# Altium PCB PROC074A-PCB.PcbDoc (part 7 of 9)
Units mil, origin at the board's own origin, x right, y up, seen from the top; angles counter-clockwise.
Board outline 2755.91 x 5300 mil, 10 copper layers (Top Layer, L2-GND, L3-SIG1, L4-GND, L5-PWR/SIG, L6-SIG2, L7-PWR2, L8-SIG3, L9-GND, Bottom Layer), stack 67.57 mil thick; 585 components, 490 nets, 2137 pads, 1150 vias.
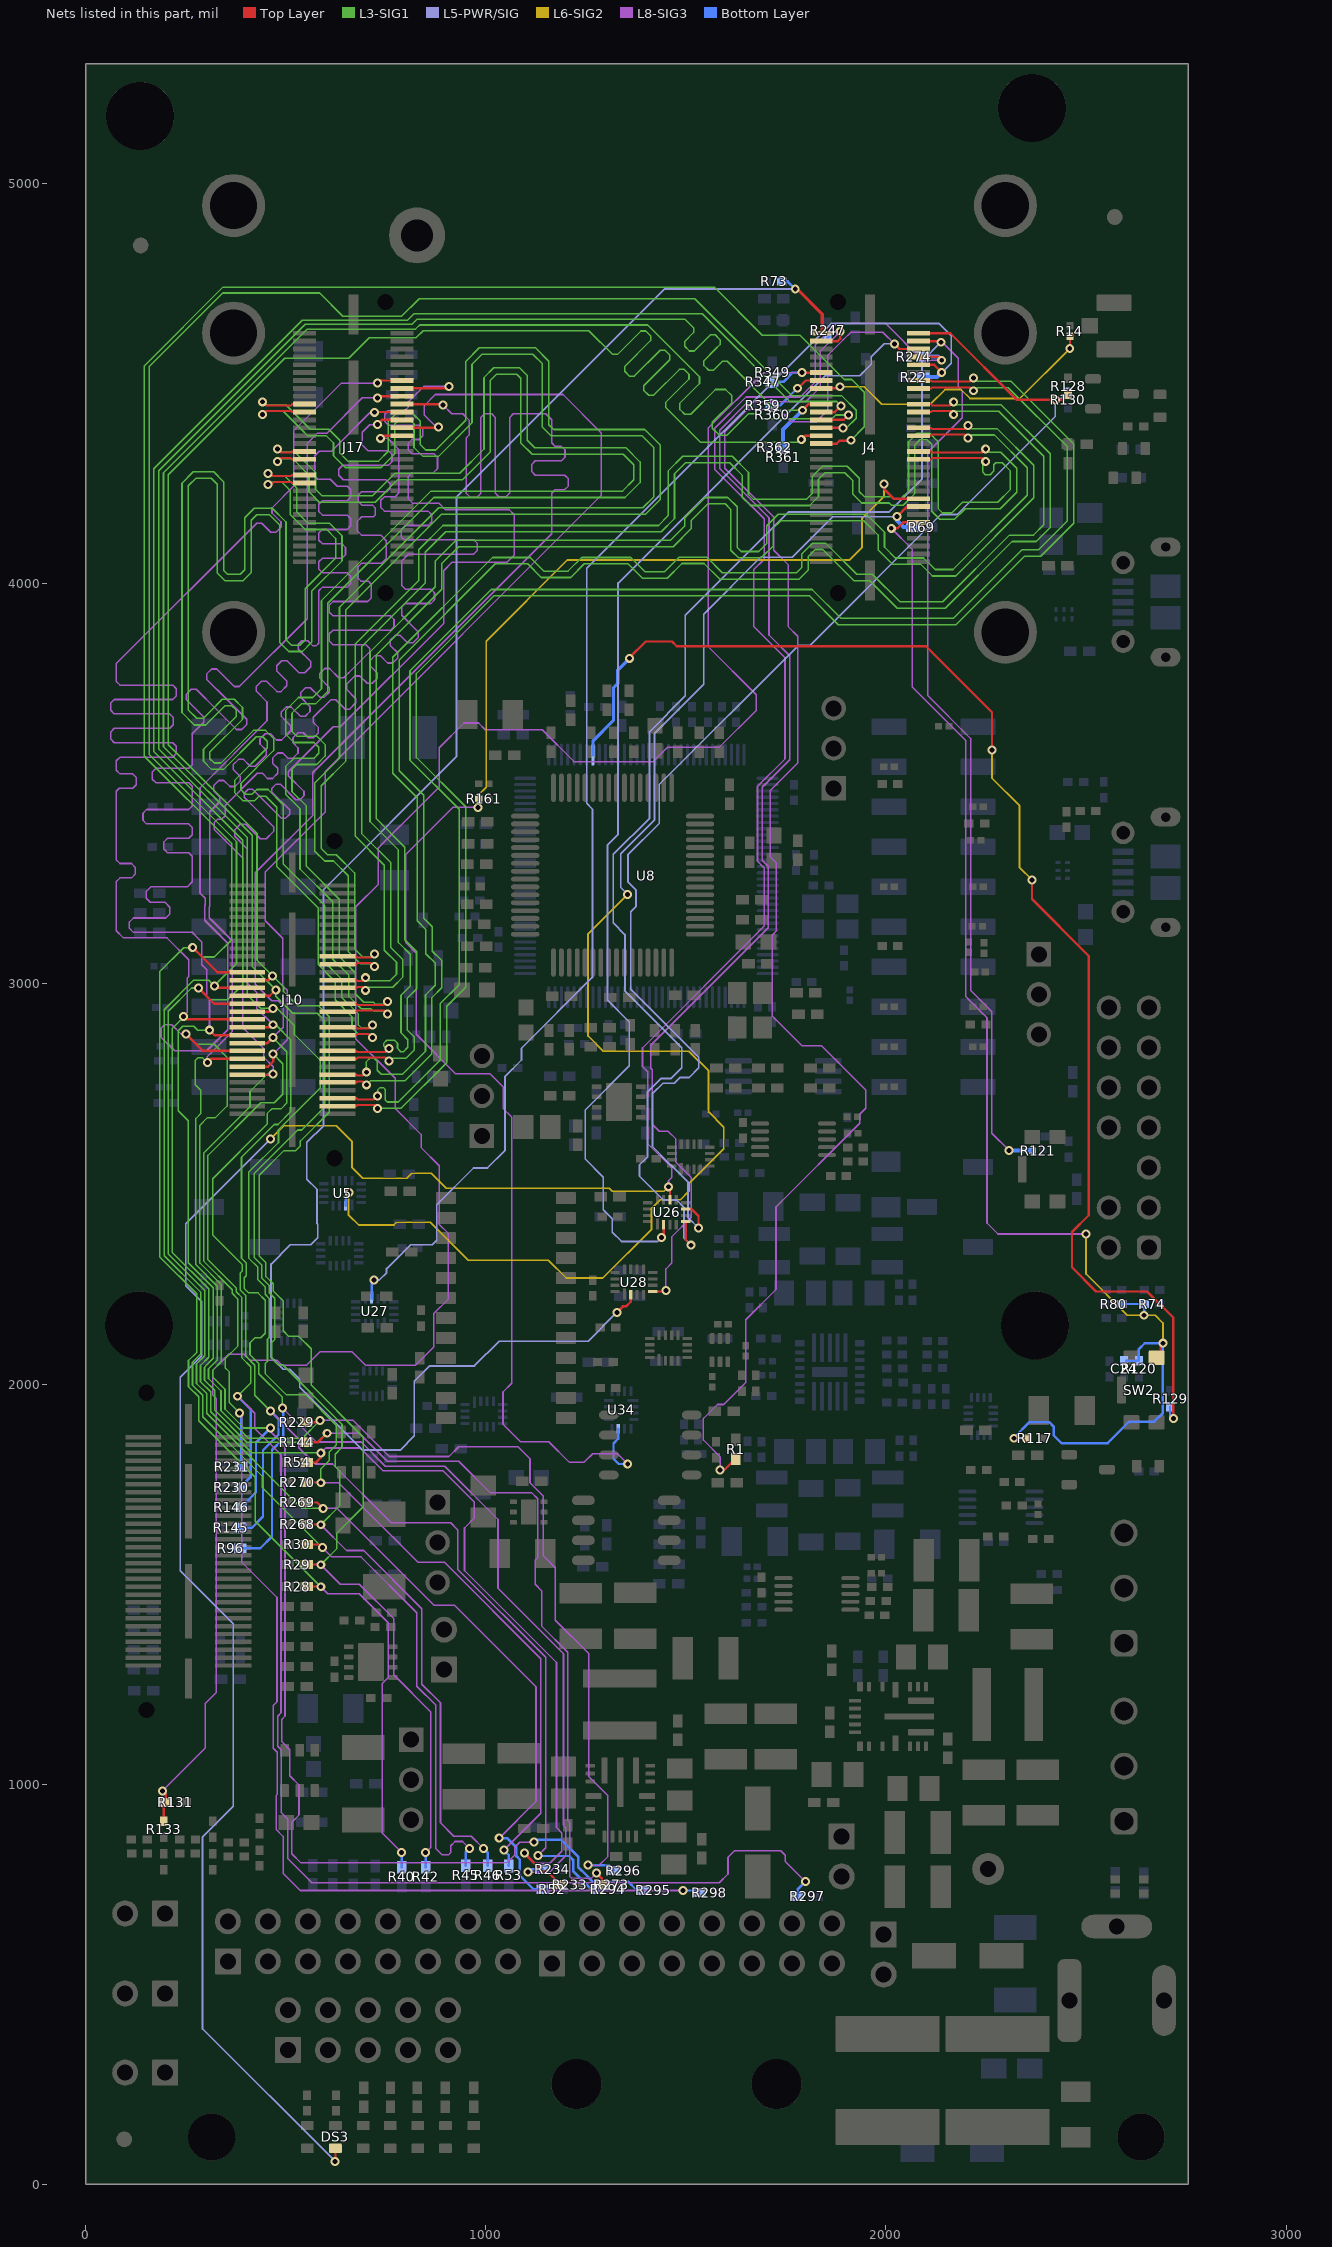
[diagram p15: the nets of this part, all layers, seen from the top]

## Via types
v1: diameter 22.4, hole 12.2, Top Layer to Bottom Layer, tented both sides, 1123 vias
v2: diameter 15.75, hole 7.87, Top Layer to Bottom Layer, tented both sides, 14 vias
v3: diameter 19.68, hole 7.87, Top Layer to Bottom Layer, tented both sides, 13 vias

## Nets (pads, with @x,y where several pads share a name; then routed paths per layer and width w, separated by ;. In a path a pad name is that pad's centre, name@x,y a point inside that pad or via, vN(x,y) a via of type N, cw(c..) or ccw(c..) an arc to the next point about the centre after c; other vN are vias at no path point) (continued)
RADAR_DP2: J4.31 J10.23 R28.1 R40.1 | length 6719.3
  Top Layer w6: v1(267.23,3090.7) 267.72,3090.7 328.94,3029.48 J10.23@403.5,3029.48 ; R28.1@551.88,1493.95 586.73,1493.95 v1(587.35,1493.32) ; J4.31@1838.5,4350.75 1877.08,4350.75 1884.59,4358.26 1911.57,4358.26 v1(1912.37,4359.06)
  L3-SIG1 w4: v1(587.35,1493.32) 423.37,1657.3 423.37,1767.21 282,1908.58 282,1967.99 256.8,1993.19 256.8,2058.81 277.09,2079.1 277.09,2225.62 184.37,2318.34 184.37,3030.23 244.84,3090.7 v1(267.23,3090.7) 290.42,3067.52 321.38,3067.52 364.57,3110.71 364.57,3350.86 146.17,3569.26 146.17,4544.88 343.14,4741.86 1571,4741.86 1691.06,4621.8 1785.04,4621.8 1896.04,4510.8 1914.4,4510.8 1945.83,4479.37 1945.83,4392.52 v1(1912.37,4359.06)
  L8-SIG3 w4: v1(587.35,1493.32) 604.62,1476.06 683.37,1476.06 755.89,1403.53 755.89,1266.58 741.37,1252.06 741.37,877.06 v1(789.37,829.06)
  Bottom Layer w6: R40.1@789.37,792.68 v1(789.37,829.06)
RADAR_DP3: J4.33 J10.25 R29.1 R42.2 | length 6663
  Top Layer w6: J10.25@403.5,3009.8 456.8,3009.8 v1(467,3020) ; R29.1@551.88,1548.95 586.73,1548.95 v1(587.35,1548.32) ; v1(1788.37,4361.06) 1797.76,4370.45 J4.33@1838.5,4370.45
  L3-SIG1 w4: v1(587.35,1548.32) 626.88,1587.85 626.88,1626.57 693.57,1693.26 693.57,1867.29 563.2,1997.66 563.2,2087.95 532.16,2119 507.27,2119 493.17,2133.1 493.17,2207.69 468.2,2232.66 468.2,2250.65 450.17,2268.68 450.17,2303.29 433.46,2320 433.46,2521.64 495.33,2583.5 524.66,2583.5 536.5,2595.34 536.5,2607.61 608.57,2679.69 608.57,2918.39 581.47,2945.49 529.87,2945.49 494.04,2981.31 494.04,2993.34 467.38,3020 v1(467,3020) 428.03,3058.97 428.03,3376.4 206.17,3598.26 206.17,4272.91 497.37,4564.11 657.37,4564.11 708.51,4615.26 825.37,4615.26 843.17,4633.06 1257.37,4633.06 1316.88,4573.55 1328.9,4573.55 1387.58,4632.23 1399.6,4632.23 1411.62,4620.21 1411.62,4608.19 1346.93,4543.49 1346.84,4543.4 1346.84,4531.38 1358.86,4519.36 1370.88,4519.36 1370.97,4519.45 1435.67,4584.14 1447.69,4584.14 1459.71,4572.12 1459.71,4560.1 1394.92,4495.32 1394.92,4483.3 1406.95,4471.28 1418.97,4471.28 1419.06,4471.37 1483.75,4536.06 1495.77,4536.06 1507.79,4524.04 1507.79,4512.02 1449.11,4453.34 1449.11,4441.32 1536.57,4353.86 1781.17,4353.86 v1(1788.37,4361.06)
  L8-SIG3 w4: v1(587.35,1548.32) 635.82,1499.86 683.57,1499.86 769.37,1414.06 769.37,1273.06 862.56,1179.87 862.56,842.25 v1(849.37,829.06)
  Bottom Layer w6: R42.2@849.37,792.68 v1(849.37,829.06)
RADAR_DP4: J4.35 J10.27 R30.1 R45.1 | length 6667
  Top Layer w6: v1(321.3,2995.29) 326.48,2990.11 J10.27@403.5,2990.11 ; R30.1@551.88,1598.95 v1@586.73,1598.95 ; J4.35@1838.5,4390.15 1892.28,4390.15 v1(1892.37,4390.06)
  L3-SIG1 w4: v1(591.37,1591.06) 441.49,1740.93 441.49,1768.65 292,1918.14 292,1972.14 266.8,1997.34 266.8,2054.66 287.09,2074.96 287.09,2229.76 286.92,2229.93 196.17,2320.68 196.17,2935.84 269.43,3009.1 307.49,3009.1 v1(321.3,2995.29) 376.57,3050.56 376.57,3355.86 158.17,3574.26 158.17,4542.74 342.43,4727 584.43,4727 642.43,4669 789.11,4669 833.11,4713 1522.43,4713 1765.57,4469.86 1889.93,4469.86 1925.57,4434.21 1925.57,4414.1 1901.52,4390.06 v1(1892.37,4390.06)
  L8-SIG3 w4: v1(591.37,1591.06) 614.57,1567.86 687.97,1567.86 827.51,1428.31 827.51,1244.74 874.46,1197.79 874.46,839.28 890.64,823.1 906.36,823.1 912.21,828.95 912.21,846.2 922.68,856.67 941.76,856.67 v1(959.37,839.06)
  Bottom Layer w6: R45.1@949.37,796.3 949.37,829.06 v1(959.37,839.06)
RADAR_DP5: J4.37 J10.29 R46.2 R268.1 | length 6602.2
  Top Layer w6: J10.29@403.5,2970.43 459.88,2970.43 v1(474.84,2985.39) ; R268.1@551.88,1648.95 586.73,1648.95 v1(587.35,1648.32) ; J4.37@1838.5,4409.85 1838.91,4410.26 1894.57,4410.26 v1(1906.37,4422.06)
  L3-SIG1 w4: v1(587.35,1648.32) 634.37,1695.34 634.37,1782.62 623.17,1793.82 623.17,1824.86 640.37,1842.06 640.37,1899.59 492,2047.96 480.62,2047.96 464.17,2064.41 464.17,2103.27 472,2111.1 472,2214.72 458.2,2228.52 458.2,2246.5 440.17,2264.53 440.17,2297.14 421.46,2315.86 421.46,2526.61 529.91,2635.06 539.73,2635.06 596.57,2691.89 596.57,2909.05 578.62,2927 517.23,2927 474.84,2969.39 v1(474.84,2985.39) 474.46,2985.39 416.03,3043.82 416.03,3371.4 194.17,3593.26 194.17,4277.89 553.28,4637 824.31,4637 834.37,4647.06 1404.57,4647.06 1534,4517.63 1534,4501 1485,4452 1485,4436 1497,4424 1512,4424 1574,4486 1599,4486 1615,4470 1615,4453 1566,4404 1566,4389 1583,4372 1603.48,4372 1656.68,4425.2 1680.23,4425.2 1692.37,4413.06 1865.37,4413.06 1874.37,4422.06 v1(1906.37,4422.06)
  L8-SIG3 w4: v1(587.35,1648.32) 651.82,1583.86 694.59,1583.86 839.89,1438.56 839.89,1249.9 886.64,1203.14 886.64,903.36 920,870 963.35,870 v1(994.3,839.06)
  Bottom Layer w6: v1(994.3,839.06) 1004.37,828.98 R46.2@1004.37,796.3
RADAR_DP6: J4.39 J10.31 R52.1 R269.1 | length 6626.5
  Top Layer w6: v1(281.29,2989.9) 320.45,2950.74 J10.31@403.5,2950.74 ; R269.1@551.88,1703.95 578.48,1703.95 v1(593.37,1689.06) ; J4.39@1838.5,4429.55 1872.18,4429.55 v1(1887.63,4445)
  L3-SIG1 w4: v1(593.37,1689.06) 539.65,1689.06 302,1926.7 302,1976.28 276.8,2001.48 276.8,2050.52 297.09,2070.81 297.09,2233.9 206.17,2324.82 206.17,2931.7 264.37,2989.9 v1(281.29,2989.9) 310.19,2961 355,2961 392.03,2998.03 392.03,3359.4 170.17,3581.26 170.17,4287.83 541.34,4659 804.31,4659 820.37,4675.06 1540.52,4675.06 1759.72,4455.86 1876.77,4455.86 v1(1887.63,4445)
  L8-SIG3 w4: v1(593.37,1689.06) 628.49,1689.06 870.49,1447.06 921.37,1447.06 1125.37,1243.06 1125.37,957.05 v1(1033.32,865)
  Bottom Layer w6: v1(1033.32,865) 1052.95,865 1076.11,841.84 1076.11,819.92 1084.8,811.23 1084.8,771.63 1119.58,736.85 R52.1@1142.75,736.85 R52.1@1152.75,736.85
RADAR_DP7: J4.41 J10.33 R53.2 R270.1 R361.1 R362.1 | length 6568.9
  Top Layer w6: J10.33@403.5,2931.06 459.46,2931.06 v1(467.46,2939.06) ; R270.1@551.88,1753.95 586.73,1753.95 v1(587.35,1753.32) ; v1(1791.37,4434.06) 1806.56,4449.25 J4.41@1838.5,4449.25
  L3-SIG1 w4: v1(587.35,1753.32) 587.35,1787.6 608.57,1808.82 608.57,1830.18 626.11,1847.72 626.11,1896.89 550.14,1972.86 501.42,1972.86 448.17,2026.1 448.17,2051 454.17,2057 454.17,2112.17 458.67,2116.67 458.67,2213.63 456.15,2216.15 456.29,2216.29 448.2,2224.37 448.2,2242.36 430.17,2260.39 430.17,2291.83 406.93,2315.07 406.93,2529.05 481.57,2603.69 481.57,2635.96 586.47,2740.87 586.47,2808.53 521.37,2873.63 521.37,2895.81 478.13,2939.06 v1(467.46,2939.06) 436.93,2939.06 404.03,2971.96 404.03,3365.4 182.17,3587.26 182.17,4282.86 548.31,4649 815.31,4649 827.37,4661.06 1498.37,4661.06 1519.09,4640.33 1519.09,4628.31 1496.9,4606.12 1496.9,4594.1 1508.92,4582.08 1520.94,4582.08 1549.15,4610.28 1561.31,4622.45 1573.33,4622.45 1585.36,4610.43 1585.36,4598.41 1573.19,4586.24 1544.99,4558.04 1544.99,4546.02 1557.01,4533.99 1569.03,4533.99 1591.22,4556.19 1603.24,4556.19 1725.37,4434.06 v1(1791.37,4434.06)
  L8-SIG3 w4: v1(587.35,1753.32) 587.62,1753.06 631.37,1753.06 829.37,1555.06 895.88,1555.06 1137.37,1313.57 1137.37,927.37 v1(1045,835)
  Bottom Layer w6: v1(1045,835) 1057.15,822.85 R53.2@1057.15,795.28
  Bottom Layer w10: R361.1@1743.25,4340 1743.25,4341 1743.25,4385.94 v1(1791.37,4434.06)
RADAR_DP8: J10.35 J17.13 R54.1 R233.1 | length 6482.3
  Top Layer w6: v1(243.78,2918.39) 250.8,2911.37 J10.35@403.5,2911.37 ; R54.1@551.88,1803.95 575.26,1803.95 587.37,1816.06 v1(587.37,1828.06) ; v1(728.63,4502) 735.08,4508.45 J17.13@790,4508.45 ; v1(1096.31,828.29) 1096.31,826.87 1140.59,782.59 1152.21,782.59 R233.1@1185.75,749.06
  L3-SIG1 w4: v1@246.37,2919.06 244.74,2917.43 216.17,2888.86 216.17,2328.97 307.09,2238.04 307.09,2066.67 286.8,2046.38 286.8,2005.62 312,1980.42 312,1930.85 414.79,1828.06 v1(587.37,1828.06)
  L8-SIG3 w4: v1(243.78,2918.39) 253.15,2927.76 253.15,3014.15 257.5,3018.5 257.5,3060.5 202.94,3115.06 94.37,3115.06 76.37,3133.06 76.37,3256.06 85.37,3265.06 114.12,3265.06 123.12,3274.06 123.12,3292.06 114.12,3301.06 85.37,3301.06 76.37,3310.06 76.37,3482.06 83.37,3489.06 117.37,3489.06 126.37,3498.06 126.37,3516.06 117.37,3525.06 85.37,3525.06 76.37,3534.06 76.37,3558.06 85.37,3567.06 217.37,3567.06 226.37,3576.06 226.37,3594.06 217.37,3603.06 71.37,3603.06 62.37,3612.06 62.37,3630.06 71.37,3639.06 209.8,3639.06 218.8,3648.06 218.8,3666.06 209.8,3675.06 71.37,3675.06 62.37,3684.06 62.37,3702.06 71.37,3711.06 217.37,3711.06 226.37,3720.06 226.37,3738.06 217.37,3747.06 85.37,3747.06 76.37,3756.06 76.37,3801.06 427.1,4151.79 439.83,4151.79 462.46,4129.16 475.18,4129.16 487.91,4141.89 487.91,4154.62 465.29,4177.24 465.29,4189.97 519.37,4244.06 519.37,4382.09 639.29,4502 v1(728.63,4502) ; v1(587.37,1828.06) 599.57,1840.26 686.26,1840.26 743.66,1782.86 893.62,1782.86 971.2,1705.28 971.2,1664.94 946.57,1640.31 946.57,1534 1176.43,1304.14 1176.43,891.5 1189.95,877.98 1189.95,832.48 1159.84,802.38 1122.22,802.38 v1(1096.31,828.29)
RADAR_DP9: J10.37 J17.15 R96.1 R234.2 | length 6552.8
  Top Layer w6: J10.37@403.5,2891.69 462,2891.69 v1(468.37,2898.06) ; J17.15@790,4488.75 903.08,4488.75 v1(907.88,4493.55)
  L3-SIG1 w4: v1(468.37,2898.06) 474.52,2898.06 512.57,2860.01 512.57,2681.1 480.32,2648.86 471.02,2648.86 389.17,2567.01 389.17,2314.47 400.87,2302.77 400.87,2270.71 395.8,2265.64 395.8,2239.05 407.05,2227.8 430.35,2227.8 448.67,2209.48 448.67,2127.31 437.42,2116.06 423.06,2116.06 410.37,2103.37 410.37,2073.49 432.57,2051.29 432.57,2025.86 491.37,1967.06 v1(491.37,1940.06)
  L8-SIG3 w4: v1(468.37,2898.06) 426.92,2939.51 426.92,2979.06 404.03,3001.95 404.03,3337 372,3369.03 372,3385 386,3399 400,3399 436,3363 451,3363 469.36,3381.36 469.36,3393 413.93,3448.44 395.95,3466.41 395.95,3476.67 406.2,3486.92 416.46,3486.92 439.56,3463.81 489.11,3414.27 499.36,3414.27 509.61,3424.52 509.61,3434.78 465.19,3479.19 465.19,3489.45 475.45,3499.7 485.7,3499.7 524.89,3460.51 535.14,3460.51 545.39,3470.77 545.39,3481.02 506.21,3520.21 506.21,3530.46 618.75,3643 636.31,3643 894.37,3901.06 894.37,4033 915.37,4054 1053,4054 1070.99,4071.99 1070.99,4173 1057.99,4186 898.06,4186 882,4202.06 816.37,4202.06 806.37,4212.06 806.37,4269 814.37,4277 868,4277 879.12,4288.12 879.12,4316.06 870.12,4325.06 815.37,4325.06 806.37,4334.06 806.37,4352.06 815.37,4361.06 833.12,4361.06 838.17,4366.1 838.17,4366.42 842.12,4370.38 842.12,4388.06 833.12,4397.06 756.15,4397.06 747.15,4406.06 747.15,4424.06 756.15,4433.06 797.37,4433.06 806.37,4442.06 806.37,4455.31 844.61,4493.55 v1(907.88,4493.55) ; v1(491.37,1940.06) 576.37,1855.06 688.43,1855.06 748.63,1794.86 897.19,1794.86 1030.37,1661.68 1030.37,1489.63 1194.02,1325.98 1194.02,896.82 1199.95,890.89 1199.95,820.81 1159.14,780 v1(1105,780)
  Bottom Layer w6: R96.1@386.25,1589.53 436.09,1589.53 465.37,1618.81 465.37,1835.06 493.57,1863.26 493.57,1937.86 v1(491.37,1940.06) ; v1(1105,780) 1112.06,787.06 R234.2@1142.75,787.06
RADAR_DP10: J10.39 J17.17 R144.1 R273.1 | length 6499.3
  Top Layer w6: v1(309.17,2884.4) 321.56,2872 J10.39@403.5,2872 ; R144.1@550.62,1855 580.31,1855 602.37,1877.06 v1(603.37,1877.06) ; v1(728.63,4465) 732.68,4469.05 J17.17@790,4469.05 ; v1(1276.22,777.47) 1289.37,764.33 R273.1@1289.37,749.06
  L3-SIG1 w4: v1(309.17,2884.4) 279.6,2884.4 269.87,2894.13 242.58,2894.13 231.33,2882.88 231.33,2683.1 256.37,2658.06 256.37,2302.91 318.8,2240.48 318.8,2064.24 296.8,2042.24 296.8,2009.76 322,1984.56 322,1934.99 402.43,1854.56 579.87,1854.56 602.37,1877.06 v1(603.37,1877.06)
  L8-SIG3 w4: v1(309.17,2884.4) 309.17,2962.83 302,2970 302,3036 290,3048 290,3104.9 266.05,3128.86 119.14,3128.86 109,3139 109,3155 119,3165 200,3165 210,3175 210,3192 198,3204 161,3204 151,3214 151,3231 163,3243 254,3243 266.37,3255.37 266.37,3319.06 257.37,3328.06 204.28,3328.06 195.28,3337.06 195.28,3355.06 204.28,3364.06 257.37,3364.06 266.37,3373.06 266.37,3391.06 257.37,3400.06 151.93,3400.06 142.93,3409.06 142.93,3427.06 151.93,3436.06 257.37,3436.06 266.37,3445.06 266.37,3494.06 257.37,3503.06 175.37,3503.06 166.37,3512.06 166.37,3530.06 175.37,3539.06 257.37,3539.06 266.37,3548.06 266.37,3626.06 294.73,3654.42 294.73,3667.15 250.89,3710.99 250.89,3723.72 263.62,3736.44 276.35,3736.44 326.55,3686.24 376.76,3636.04 389.49,3636.04 402.21,3648.76 402.21,3661.49 352.01,3711.7 301.81,3761.9 301.81,3774.63 314.53,3787.36 327.26,3787.36 371.1,3743.52 383.83,3743.52 553.37,3913.06 553.37,4351.06 579.37,4377.06 603.37,4377.06 691.31,4465 v1(728.63,4465) ; v1(603.37,1877.06) 683.4,1877.06 753.6,1806.86 932.42,1806.86 1010.57,1728.7 1114.2,1728.7 1129.42,1713.48 1129.42,1566.37 1123.34,1560.29 1123.34,1499.41 1139.2,1483.55 1139.2,1395.28 1204.8,1329.68 1204.8,909 1209.95,903.85 1209.95,768.95 1213.8,765.1 1263.85,765.1 v1(1276.22,777.47)
RADAR_DP11: J10.41 J17.19 R145.1 R294.2 | length 6540.8
  Top Layer w6: J10.41@403.5,2852.32 453.82,2852.32 v1(467.5,2866) ; J17.19@790,4449.35 890.28,4449.35 v1(892.63,4447)
  L3-SIG1 w4: v1(461.37,1933.06) 422.57,1971.86 422.57,2047.15 400.2,2069.52 400.2,2220.51 385.8,2234.9 385.8,2277.65 390.87,2282.72 390.87,2298.62 317.17,2372.32 317.17,2513.39 453.17,2649.39 453.17,2676.01 465.76,2688.6 488.87,2688.6 502.57,2702.3 502.57,2830.93 v1(467.5,2866)
  L8-SIG3 w4: v1(461.37,1933.06) 532.37,1862.06 532.37,1841.06 573.17,1800.26 616.74,1800.26 763.8,1653.2 912.02,1653.2 929.21,1636.01 929.21,1537.21 1149.37,1317.06 1149.37,840.77 v1(1130.17,821.58) ; v1(467.5,2866) 493.37,2891.87 493.37,2946.06 481.17,2958.26 464.69,2958.26 423.8,2999.15 423.8,3277.68 567.37,3421.25 567.37,3528.06 1164.37,4125.06 1164.37,4226.7 1173.37,4235.7 1197.37,4235.7 1206.37,4244.7 1206.37,4262.7 1197.37,4271.7 1123.37,4271.7 1114.37,4280.7 1114.37,4298.7 1123.37,4307.7 1188.83,4307.7 1197.83,4316.7 1197.83,4334.7 1188.83,4343.7 1173.37,4343.7 1164.37,4352.7 1164.37,4410.06 1149.37,4425.06 1068.37,4425.06 1059.37,4416.06 1059.37,4227.08 1050.37,4218.08 1032.37,4218.08 1023.37,4227.08 1023.37,4416.06 1014.37,4425.06 996.37,4425.06 987.37,4416.06 987.37,4226.06 978.37,4217.06 960.37,4217.06 951.37,4226.06 951.37,4365.39 958,4372.02 958,4409.43 942.37,4425.06 914.57,4425.06 v1(892.63,4447)
  Bottom Layer w6: R145.1@386.25,1640.53 414.85,1640.53 442.92,1668.61 442.92,1834.61 481.57,1873.26 481.57,1912.86 v1(461.37,1933.06) ; v1(1130.17,821.58) 1131.52,820.23 1208.47,820.23 1218,810.7 1218,782.43 1263.58,736.85 R294.2@1281.37,736.85
RADAR_DP12: J10.43 J17.21 R146.1 R295.1 | length 6654.2
  Top Layer w6: v1(250.53,2874.93) 292.83,2832.63 J10.43@403.5,2832.63 ; v1(721.63,4429) 722.28,4429.65 J17.21@790,4429.65
  L3-SIG1 w4: v1@250.24,2875.73 250.78,2875.19 276.88,2849.09 321.11,2849.09 353.07,2817.13 353.07,2695.07 324,2666 304,2666 285.17,2647.17 285.17,2302.39 338.8,2248.76 338.8,2055.95 316.8,2033.95 316.8,2018.05 347.81,1987.04 347.81,1937.47 395.22,1890.06 v1(461.37,1890.06)
  L8-SIG3 w4: v1(250.53,2874.93) 238.07,2874.93 215,2898 196.57,2898 188,2889.43 188,2867 222,2833 302.44,2833 355,2885.56 355,3101.71 297.23,3159.48 297.23,3197.18 298.23,3198.18 298.23,3214.18 285.37,3227.04 285.37,3490.06 453,3657.69 453,3704.88 426.39,3731.49 426.39,3744.22 439.12,3756.94 451.85,3756.94 478,3730.79 487.79,3730.79 502.35,3745.35 502.35,3757.35 477.31,3782.4 477.31,3795.13 490.03,3807.86 502.76,3807.86 532.62,3778 547,3778 562,3793 562,3806 531,3837 531,3849 540,3858 555,3858 568,3845 575.57,3845 582.37,3851.8 582.37,3983.08 591.37,3992.08 653.37,3992.08 662.37,4001.08 662.37,4019.08 653.37,4028.08 591.37,4028.08 582.37,4037.08 582.37,4055.08 591.37,4064.08 640.17,4064.08 649.17,4073.08 649.17,4091.08 640.17,4100.08 591.37,4100.08 582.37,4109.08 582.37,4127.08 591.37,4136.08 653.37,4136.08 662.37,4145.08 662.37,4163.08 653.37,4172.08 591.37,4172.08 582.37,4181.08 582.37,4199.08 591.37,4208.08 653.37,4208.08 662.37,4217.08 662.37,4235.08 653.37,4244.08 628.32,4244.08 611.14,4261.26 579.74,4261.26 572,4269 572,4320 583.8,4331.8 614.11,4331.8 711.31,4429 v1(721.63,4429) ; v1(461.37,1890.06) 461.37,1881.86 498,1845.23 498,1170.17 490.18,1162.35 490.18,1105.92 510,1086.1 510,1021 533,998 533,923 515,905 515,826 538,803 1052,803 1072,823 1072,842 1085,855 v1(1120,855)
  Bottom Layer w6: R146.1@387.49,1691.53 425.37,1729.41 425.37,1854.06 v1(461.37,1890.06) ; v1(1120,855) 1125.63,860.63 1188.57,860.63 1231.21,817.99 1231.21,791.59 1237.8,785 1238.5,785 1266.84,756.66 1355.19,756.66 1377.03,734.82 R295.1@1395.34,734.82
RADAR_DP13: J10.45 J17.23 R229.1 R296.2 | length 6580
  Top Layer w6: v1(303.96,2803.55) 313.36,2812.95 J10.45@403.5,2812.95 ; R229.1@551.25,1904.53 580.85,1904.53 v1(585.37,1909.06) ; v1(728.63,4398) 740.58,4409.95 J17.23@790,4409.95
  L3-SIG1 w4: v1(303.96,2803.55) 291.9,2815.61 280.33,2815.61 273.37,2808.65 273.37,2748.06 287.37,2734.06 287.37,2676.06 275.17,2663.86 275.17,2298.25 328.8,2244.62 328.8,2060.09 306.8,2038.09 306.8,2013.91 337.81,1982.9 337.81,1933.32 406.58,1864.56 540.87,1864.56 v1(585.37,1909.06)
  L8-SIG3 w4: v1(303.96,2803.55) 303.96,2818.96 366,2881 366,3107.86 308.23,3165.64 308.23,3192.62 310,3194.39 310,3430.69 334.73,3455.42 334.73,3468.15 319.63,3483.25 319.63,3495.98 332.36,3508.71 345.08,3508.71 360.19,3493.6 372.92,3493.6 385.65,3506.33 385.65,3519.06 368.83,3535.88 368.83,3548.6 381.56,3561.33 394.28,3561.33 411.1,3544.52 423.83,3544.52 450.93,3571.62 450.93,3584.34 435.5,3599.78 435.5,3612.51 448.22,3625.24 460.95,3625.24 476.39,3609.8 489.11,3609.8 506.31,3627 512.32,3633.01 512.32,3645.03 488.99,3668.37 488.99,3680.39 501.01,3692.41 513.03,3692.41 536.37,3669.07 548.39,3669.07 560.41,3681.09 560.41,3693.11 537.07,3716.45 537.07,3728.47 549.09,3740.49 561.11,3740.49 584.45,3717.16 596.47,3717.16 608.49,3729.18 608.49,3741.2 585.16,3764.53 585.16,3776.55 597.18,3788.57 609.2,3788.57 632.53,3765.24 644.55,3765.24 656.57,3777.26 692.64,3813.32 709.37,3830.06 709.37,3839.06 700.37,3848.06 617.63,3848.06 608.63,3857.06 608.63,3875.06 617.63,3884.06 761.35,3884.06 770.35,3893.06 770.35,3911.06 761.35,3920.06 617.63,3920.06 608.63,3929.06 608.63,3947.06 617.63,3956.06 705.06,3956.06 713.82,3964.81 713.82,3999.19 706,4007 687.66,4007 680,4014.66 680,4042 690,4052 740,4052 751,4063 751,4108 737,4122 689,4122 678,4133 678,4156 690,4168 719,4168 723.37,4172.37 723.37,4189.97 716.34,4197 690,4197 681,4206 681,4222 689,4230 752,4230 761,4239 761,4250 750.5,4260.5 643.5,4260.5 632.53,4271.47 632.53,4286.53 642.5,4296.5 756.39,4296.5 765.39,4305.5 765.39,4323.5 756.39,4332.5 705.5,4332.5 691,4347 691,4379 710,4398 v1(728.63,4398) ; v1(585.37,1909.06) 668.37,1909.06 758.57,1818.86 907.68,1818.86 932.07,1843.25 1080.06,1843.25 1110.2,1813.11 1110.2,1753.28 1143.81,1719.67 1143.81,1570.92 1173.72,1541.01 1173.72,1409.71 1257,1326.43 1257,1019 1305,971 1305,819.19 1283.49,797.67 v1(1255,797.67)
  Bottom Layer w6: v1(1255,797.67) 1306.54,797.67 R296.2@1320.16,784.06
RADAR_DP14: J10.47 J17.25 R230.1 R297.1 | length 6632
  Top Layer w6: J10.47@403.5,2793.26 455.26,2793.26 468.37,2806.37 v1(468.37,2825.06) ; J17.25@790,4390.25 879.88,4390.25 v1(881.63,4392)
  L3-SIG1 w4: v1(379.37,1969.52) 412.57,2002.72 412.57,2043.01 390.2,2065.38 390.2,2216.36 375.8,2230.76 375.8,2240.05 305.17,2310.68 305.17,2571.17 437.14,2703.14 471,2703.14 492.57,2724.71 492.57,2800.86 v1(468.37,2825.06)
  L8-SIG3 w4: v1(379.37,1969.52) 422,1926.89 422,1889 488,1823 488,1178.21 479.69,1169.9 479.69,1094.91 488.57,1086.03 488.57,967.72 488.42,967.57 488.42,928.97 505,912.4 505,814 566,753 1424,753 1424.19,753.19 1583.08,753.19 1605.17,775.28 1605.17,817.01 1621.42,833.26 1737.32,833.26 1748.57,822.01 1748.57,806.35 v1(1798.45,756.48) ; v1(468.37,2825.06) 503.37,2860.06 503.37,2984.01 492.37,2995.01 492.37,3114.06 448.52,3157.9 448.52,3279.77 598.37,3429.62 598.37,3531.36 1288,4220.99 1288,4378 1192.65,4473.35 873.66,4473.35 846.37,4446.06 846.37,4421.48 875.85,4392 v1(881.63,4392)
  Bottom Layer w6: v1(379.37,1969.52) 411.99,1936.89 411.99,1767.28 R230.1@387.25,1742.53 ; R297.1@1779.86,719.8 1779.86,737.89 v1(1798.45,756.48)
RADAR_DP15: J10.49 J17.27 R231.1 R298.2 | length 6559.6
  Top Layer w6: J10.49@403.5,2773.58 466.89,2773.58 v1(468.37,2775.06) ; v1(736.63,4364) 743.18,4370.55 J17.27@790,4370.55
  L3-SIG1 w4: v1(384.37,1928.06) 358.92,1953.5 358.92,2030.23 348.8,2040.35 348.8,2063.6 380.2,2095 380.2,2212.22 365.8,2226.62 365.8,2235.9 295.17,2306.53 295.17,2578.17 410.37,2693.37 410.37,2731.38 454.05,2775.06 v1(468.37,2775.06)
  L8-SIG3 w4: v1(384.37,1928.06) 389.37,1923.06 389.37,1555.06 478,1466.43 478,1205.65 468.67,1196.32 468.67,1089.48 478.57,1079.58 478.57,974.69 476.42,972.54 476.42,885.68 493.1,869 493.1,776.9 536.01,733.99 v1(1492.25,733.99) ; v1(468.37,2775.06) 468.37,2793.26 444.37,2817.26 444.37,2839.06 392.03,2891.4 392.03,3314.97 321,3386 321,3403.45 329.17,3411.62 339.37,3411.62 348.37,3420.62 348.37,3446.06 428.69,3526.38 441.42,3526.38 454.09,3513.7 466.82,3513.7 479.55,3526.43 479.55,3539.16 466.87,3551.83 466.87,3564.56 479.6,3577.29 492.33,3577.29 505.01,3564.61 517.73,3564.61 530.46,3577.34 530.46,3590.07 517.79,3602.74 517.79,3615.47 530.51,3628.2 543.24,3628.2 555.92,3615.52 568.65,3615.52 581.37,3628.25 581.37,3640.98 568.7,3653.65 568.7,3666.38 612.66,3710.34 624.83,3710.34 648.17,3687 659,3687 675,3703 675,3713 652,3736 652,3749.69 672.19,3769.88 684.92,3769.88 703.38,3751.42 716.11,3751.42 728.83,3764.14 728.83,3776.87 710.37,3795.33 710.37,3808.06 723.1,3820.79 735.83,3820.79 754.29,3802.33 767.02,3802.33 779.74,3815.06 779.74,3827.78 761.29,3846.24 761.29,3858.97 774,3871.69 785.31,3871.69 804,3853 818,3853 831,3866 831,3880 789.37,3921.63 789.37,3942.06 798.37,3951.06 862.61,3951.06 871.61,3960.06 871.61,3978.06 862.61,3987.06 798.37,3987.06 789.37,3996.06 789.37,4057.43 806,4074.06 969.06,4074.06 978,4083 978,4102 969.94,4110.06 795.94,4110.06 788.06,4117.94 788.06,4135.69 798.43,4146.06 855.39,4146.06 864.39,4155.06 864.39,4173.06 855.39,4182.06 746.43,4182.06 737.43,4191.06 737.43,4209.06 746.43,4218.06 773.35,4218.06 782.35,4227.06 782.35,4336.08 754.43,4364 v1(736.63,4364)
  Bottom Layer w6: v1(384.37,1928.06) 388.25,1924.18 R231.1@388.25,1793.53 ; v1(1492.25,733.99) 1529.29,733.99 R298.2@1534.22,729.06
RADAR_GPIO_0: J4.56 R1.2 U26.2 | length 6646.9
  Top Layer w6: v1(1439.37,2366.06) 1444.37,2371.06 U26.2@1444.37,2398.06 ; v1(1585.44,1785.6) 1596.37,1785.6 R1.2@1624,1813.23 R1.2@1626.93,1813.23 ; v1(2021.37,4600.06) 2034.28,4587.15 J4.56@2081.5,4587.15
  L5-PWR/SIG w4.5: v1(1439.37,2366.06) 1429.58,2356.27 1339.33,2356.27 1316,2379.6 1316,2413.06 1293.54,2435.52 1293.54,2517.28 1248.38,2562.44 1248.38,2685.07 1358.57,2795.26 1358.57,2904.86 1304.37,2959.06 1304.37,3348.06 1330.37,3374.06 1330.37,4002.06 1848.37,4520.06 1934.37,4520.06 1963.37,4549.06 1963.37,4567.31 1996.12,4600.06 v1(2021.37,4600.06)
  L8-SIG3 w4: v1(1585.44,1785.6) 1585.44,1818.56 1543.78,1860.22 1543.78,1913.78 1579,1949 1594.51,1949 1649.37,2003.86 1649.37,2160.68 1725.17,2236.48 1725.17,2442.42 1934.37,2651.62 1934.37,2674.49 1949.57,2689.69 1949.57,2734.86 1838.37,2846.06 1789.79,2846.06 1715.8,2920.05 1715.8,3122.07 1726,3132.27 1726,3302.43 1710.8,3317.63 1710.8,3483.37 1779.57,3552.14 1779.57,3869.43 1755.37,3893.63 1755.37,4048.26 1719.57,4084.06 1719.57,4167.15 1597.37,4289.35 1597.37,4380.17 1652.2,4435 1733.63,4435 1763.63,4405 1825.45,4405 1855,4434.55 1855,4571.94 1893.86,4610.8 1894,4610.8 1912.4,4629.2 1992.23,4629.2 v1(2021.37,4600.06) ; v1@2021.37,4598 v1@2026.63,4598
RADAR_GPIO_1: J4.58 R121.2 U26.5 | length 5289.7
  Top Layer w6: U26.5@1499.49,2405.93 1499.49,2360.67 v1(1513.1,2347.06) ; J4.58@2081.5,4606.85 2134.58,4606.85 v1(2137.37,4604.06)
  L5-PWR/SIG w4.5: v1(1513.1,2347.06) 1495,2365.16 1495,2441.86 1476.86,2460 1443.86,2460 1384,2519.86 1384,2548.33 1404.17,2568.5 1404.17,2730.39 1437.83,2764.06 1462.94,2764.06 1489.57,2790.69 1489.57,2840.86 1347.57,2982.86 1347.57,3123.42 1318.37,3152.62 1318.37,3323.8 1409.2,3414.63 1409.2,3630.89 1498.37,3720.06 1498.37,3921.49 1756.88,4180 2007.99,4180 2090.37,4262.38 2090.37,4557.06 v1(2137.37,4604.06)
  L8-SIG3 w4: v1(2137.37,4604.06) 2140.8,4604.06 2180.83,4564.03 2180.83,4491.77 2190.37,4482.23 2190.37,4415.06 2104.43,4329.12 2104.43,3720.94 2211.57,3613.8 2211.57,2984.43 2264.57,2931.43 2264.57,2626.86 v1(2307.37,2584.06)
  Bottom Layer w10: v1(2307.37,2584.06) 2364.94,2584.06 R121.2@2366,2583
RADAR_GPIO_2: J4.60 R128.1 R130.2 U26.7 | length 3321
  Top Layer w6: U26.7@1499.49,2437.43 1514,2437.43 1531.37,2420.06 v1(1531.37,2390.06) ; J4.60@2081.5,4626.55 2160.88,4626.55 2327.37,4460.06 v1(2423.37,4460.06) 2441.05,4460.06 R128.1@2455.37,4474.37
  L5-PWR/SIG w4.5: v1(1531.37,2390.06) 1505.57,2415.86 1505.57,2504.42 1416.17,2593.82 1416.17,2725.42 1442.8,2752.06 1470.37,2752.06 1484.37,2766.06 1507.62,2766.06 1532.13,2790.56 1532.13,2817.29 1362.17,2987.26 1362.17,3180.89 1375.37,3194.09 1375.37,3234.63 1355,3255 1355,3322.69 1433.37,3401.06 1433.37,3498.62 1780.6,3845.86 1809.17,3845.86 2136.76,4173.45 2178.33,4173.45 2423.37,4418.49 v1(2423.37,4460.06)
  Bottom Layer w6: v1(2423.37,4460.06) 2435.37,4460.06 R130.2@2455,4479.69
RADAR_HOSTINTR1: J4.16 R69.2 U5.2 | length 3711
  Top Layer w6: v1(2027.41,4168) 2052.56,4193.15 J4.16@2081.5,4193.15
  L5-PWR/SIG w4.5: v1(1354.37,3224.06) 1337.3,3241.13 1337.3,3325.76 1421.2,3409.66 1421.2,3625.92 1544.57,3749.29 1544.57,3924.63 1686.44,4066.5 1765.5,4066.5 1867,4168 v1(2027.41,4168)
  L6-SIG2 w4.5: v1@656.37,2476 656.37,2423.63 682.81,2397.19 769.28,2397.19 776.58,2404.49 861.25,2404.49 956.34,2309.4 1156.17,2309.4 1200.58,2264.99 1291.84,2264.99 1414.17,2387.32 1414.17,2439.42 1435.6,2460.86 1486.37,2460.86 1507.37,2481.86 1507.37,2500.52 1594.57,2587.72 1594.57,2642.29 1556.57,2680.29 1556.57,2782.86 1507.59,2831.84 1293.59,2831.84 1255.37,2870.06 1255.37,3125.06 v1(1354.37,3224.06)
  Bottom Layer w6: U5.2@649.5,2445.5 649.5,2469.13 v1@656.37,2476
  Bottom Layer w10: v1(2027.41,4168) 2027.41,4158.45 2043.87,4141.99 R69.2@2066.38,4141.99
  other v1: 658.37,2479
RADAR_LVDS_0M: J4.48 J10.58 | length 3885.9
  Top Layer w5.01: J10.58@629.09,2694.84 676.28,2694.84 679.12,2697.68 720.67,2697.68 v1(729.37,2688.98) ; J4.48@2081.5,4508.35 2112.5,4508.35 2115.35,4505.5 2209.67,4505.5 v1(2218.37,4514.2)
  L3-SIG1 w4.01: v1(729.37,2688.98) 729.45,2689.06 787.67,2689.06 901.98,2803.37 901.98,2944.3 949.37,2991.69 949.37,3443.06 826.37,3566.06 826.37,3776.26 1020.17,3970.06 1808.74,3970.06 1880.8,3898 2175.31,3898 2346.31,4069 2387.04,4069 2469.57,4151.53 2469.57,4349.48 2312.56,4506.5 2262,4506.5 2226.07,4506.5 v1(2218.37,4514.2)
RADAR_LVDS_0P: J4.46 J10.56 | length 3880.4
  Top Layer w5.01: J10.56@629.09,2714.52 676.28,2714.52 679.12,2711.68 720.67,2711.68 v1(729.37,2720.38) ; J4.46@2081.5,4488.65 2112.5,4488.65 2115.35,4491.5 2209.67,4491.5 v1(2218.37,4482.8)
  L3-SIG1 w4.01: v1(729.37,2720.38) 729.37,2735.24 735.19,2741.06 743.87,2741.06 748.5,2736.43 748.5,2710.13 753.57,2705.06 781.04,2705.06 885.98,2810 885.98,2950.93 933.37,2998.32 933.37,3436.43 810.37,3559.43 810.37,3782.88 1013.54,3986.06 1815.37,3986.06 1887.43,3914 2168.69,3914 2339.69,4085 2380.41,4085 2453.57,4158.16 2453.57,4342.86 2305.93,4490.5 2226.07,4490.5 v1(2218.37,4482.8)
RADAR_LVDS_1M: J4.42 J10.52 | length 3879.3
  Top Layer w5.01: J10.52@629.09,2753.89 676.28,2753.89 679.12,2756.74 692.67,2756.74 v1(701.37,2748.04) ; J4.42@2081.5,4449.25 2112.5,4449.25 2115.35,4446.4 2160.67,4446.4 v1(2169.37,4455.1)
  L3-SIG1 w4.01: v1(701.37,2748.04) 711.39,2758.06 798,2758.06 865.19,2825.24 865.19,2966.03 889.37,2990.22 889.37,3058.79 866.01,3082.14 866.01,3142.96 844.37,3164.6 844.37,3472.06 783.37,3533.06 783.37,3810.03 1023.4,4050.06 1104.37,4050.06 1138.37,4016.06 1212,4016.06 1246,4050.06 1355.37,4050.06 1391.37,4014.06 1453,4014.06 1490,4051.06 1545.37,4051.06 1584.37,4012.06 1783,4012.06 1805.37,4034.43 1805.37,4068.06 1823.37,4086.06 1842.37,4086.06 1920.37,4008.06 1959.32,4008.06 2028.32,3939.06 2148.37,3939.06 2315.31,4106 2375.47,4106 2410.37,4140.9 2410.37,4325.4 2288.37,4447.4 2177.07,4447.4 v1(2169.37,4455.1)
RADAR_LVDS_1P: J4.40 J10.50 | length 3883.3
  Top Layer w5.01: J10.50@629.09,2773.58 676.28,2773.58 679.12,2770.74 692.67,2770.74 v1(701.37,2779.44) ; J4.40@2081.5,4429.55 2112.5,4429.55 2115.35,4432.4 2160.67,4432.4 v1(2169.37,4423.7)
  L3-SIG1 w4.01: v1(701.37,2779.44) 701.37,2806.06 711.1,2815.79 719.37,2815.79 728.37,2806.79 728.37,2784.06 738.37,2774.06 791.37,2774.06 849.19,2831.87 849.19,2972.66 873.37,2996.84 873.37,3052.16 850.01,3075.52 850.01,3136.33 828.37,3157.97 828.37,3465.43 767.37,3526.43 767.37,3816.65 1016.77,4066.06 1111,4066.06 1145,4032.06 1205.37,4032.06 1239.37,4066.06 1362,4066.06 1398,4030.06 1446.37,4030.06 1483.37,4067.06 1552,4067.06 1591,4028.06 1776.37,4028.06 1789.37,4041.06 1789.37,4074.68 1816.74,4102.06 1849,4102.06 1927,4024.06 1965.95,4024.06 2034.95,3955.06 2141.74,3955.06 2308.69,4122 2368.84,4122 2394.37,4147.53 2394.37,4318.77 2281.74,4431.4 2177.07,4431.4 v1(2169.37,4423.7)
RADAR_LVDS_2M: J10.40 J17.40 | length 3852.7
  Top Layer w5.01: v1(455.37,4248.05) 463.85,4248.05 471,4255.2 513.15,4255.2 516,4252.35 J17.40@547,4252.35 ; J10.40@629.09,2872 676.28,2872 679.12,2874.85 707.67,2874.85 v1(716.37,2866.15)
  L3-SIG1 w4.01: v1(455.37,4248.05) 461.52,4254.2 490.23,4254.2 511.37,4233.06 511.37,4173 548.37,4136 602.06,4136 624.37,4113.69 624.37,4064.06 548.37,3988.06 548.37,3860.52 534.85,3847 514,3847 500.37,3860.63 500.37,4154.68 466,4189.06 420.74,4189.06 397.37,4165.68 397.37,4035.06 386.37,4024.06 354.37,4024.06 344.37,4034.06 344.37,4255.68 320,4280.06 268.74,4280.06 240.37,4251.68 240.37,3678.43 270.68,3648.12 271.51,3647.29 299.81,3647.29 317.29,3664.77 348.02,3695.5 364.72,3695.5 375.59,3684.63 375.59,3667.92 294.1,3586.43 294.1,3556.47 314.34,3536.22 344.3,3536.22 425.8,3617.72 442.5,3617.72 453.37,3606.85 453.37,3590.14 371.88,3508.65 371.88,3478.68 392.12,3458.44 422.09,3458.44 432.87,3469.22 449.58,3469.22 477.18,3441.61 477.18,3293.45 581.37,3189.26 581.37,3047.9 623.37,3005.9 623.37,2960.22 665.37,2918.22 665.37,2890.64 682.16,2873.85 708.67,2873.85 v1(716.37,2866.15)
RADAR_LVDS_2P: J10.38 J17.38 | length 3852.7
  Top Layer w5.01: v1(455.37,4276.35) 461.85,4276.35 469,4269.2 513.15,4269.2 516,4272.05 J17.38@547,4272.05 ; J10.38@629.09,2891.69 676.28,2891.69 679.12,2888.85 707.67,2888.85 v1(716.37,2897.55)
  L3-SIG1 w4.01: v1(455.37,4276.35) 461.52,4270.2 496.86,4270.2 527.37,4239.68 527.37,4179.63 555,4152 608.68,4152 640.37,4120.31 640.37,4057.43 564.37,3981.43 564.37,3853.89 541.48,3831 507.37,3831 484.37,3854 484.37,4148.06 459.37,4173.06 427.37,4173.06 413.37,4159.06 413.37,4028.43 393,4008.06 347.74,4008.06 328.37,4027.43 328.37,4249.06 313.37,4264.06 275.37,4264.06 256.37,4245.06 256.37,3685.06 277.3,3664.12 294.01,3664.12 310.66,3680.77 341.39,3711.5 371.35,3711.5 391.59,3691.25 391.59,3661.29 310.1,3579.8 310.1,3563.09 320.97,3552.22 337.68,3552.22 419.17,3633.72 449.13,3633.72 469.37,3613.47 469.37,3583.51 387.88,3502.02 387.88,3485.31 398.75,3474.44 415.46,3474.44 427.07,3486.05 455.37,3486.05 493.18,3448.24 493.18,3300.08 597.37,3195.89 597.37,3054.53 639.37,3012.53 639.37,2966.85 681.37,2924.85 681.37,2897.26 688.79,2889.85 708.67,2889.85 v1(716.37,2897.55)
RADAR_LVDS_3M: J10.34 J17.34 | length 3888.9
  Top Layer w5.01: v1(479.37,4305.6) 488.07,4314.3 513.15,4314.3 516,4311.45 J17.34@547,4311.45 ; J10.34@629.09,2931.06 676.28,2931.06 679.12,2933.9 745.67,2933.9 v1(754.37,2925.2)
  L3-SIG1 w4.01: v1(479.37,4305.6) 487.07,4313.3 516.5,4313.3 558,4271.8 558,4230 583.69,4204.31 723.26,4204.31 779.29,4260.35 941.29,4260.35 1011.37,4330.43 1011.37,4509.06 1026.37,4524.06 1077.37,4524.06 1087.37,4514.06 1087.37,4352.43 1115.74,4324.06 1343.37,4324.06 1369.37,4298.06 1369.37,4260.06 1341.37,4232.06 862.74,4232.06 589.06,3958.37 589.06,3737.74 567.37,3716.06 531.74,3716.06 499.37,3683.68 499.37,3624.74 520.56,3603.56 570.32,3603.56 582.14,3591.74 582.14,3576.37 570.32,3564.56 520.56,3564.56 499.37,3543.37 499.37,3474.06 535.37,3438.06 535.37,3287.3 617.37,3205.3 617.37,3061.85 657.63,3021.6 657.63,2968.6 688.17,2938.06 712.59,2938.06 717.74,2932.9 746.67,2932.9 v1(754.37,2925.2)
RADAR_LVDS_3P: J10.32 J17.32 | length 3888.9
  Top Layer w5.01: v1(479.37,4337) 488.07,4328.3 513.15,4328.3 516,4331.15 J17.32@547,4331.15 ; J10.32@629.09,2950.74 676.28,2950.74 679.12,2947.9 745.67,2947.9 v1(754.37,2956.6)
  L3-SIG1 w4.01: v1(479.37,4337) 487.07,4329.3 523.13,4329.3 574,4278.43 574,4236.63 590.31,4220.31 716.63,4220.31 772.66,4276.35 934.66,4276.35 995.37,4337.06 995.37,4515.68 1019.74,4540.06 1084,4540.06 1103.37,4520.68 1103.37,4359.06 1122.37,4340.06 1350,4340.06 1385.37,4304.68 1385.37,4253.43 1348,4216.06 869.37,4216.06 605.06,3951.74 605.06,3795.74 605.06,3737.74 605.06,3731.11 574,3700.06 538.37,3700.06 515.37,3677.06 515.37,3631.37 527.18,3619.56 576.95,3619.56 598.14,3598.37 598.14,3569.74 576.95,3548.56 527.18,3548.56 515.37,3536.74 515.37,3480.68 551.37,3444.68 551.37,3293.93 633.37,3211.93 633.37,3068.48 673.63,3028.22 673.63,2975.23 694.8,2954.06 719.21,2954.06 724.37,2948.9 746.67,2948.9 v1(754.37,2956.6)
RADAR_LVDS_CLKM: J4.36 J10.46 | length 3858.5
  Top Layer w5.01: J10.46@629.09,2812.95 676.28,2812.95 679.12,2815.79 748.67,2815.79 v1(757.37,2807.09) ; J4.36@2081.5,4390.15 2112.5,4390.15 2115.35,4387.3 2196.67,4387.3 v1(2205.37,4396)
  L3-SIG1 w4.01: v1(757.37,2807.09) 765.07,2814.79 777.95,2814.79 800.73,2814.79 821,2835.06 821,2867.53 803.76,2884.77 803.76,2965.02 827.06,2988.31 827.06,3080.72 797.37,3110.4 797.37,3341.68 726.37,3412.68 726.37,3823.06 889.74,3986.43 889.74,4050.8 932,4093.06 1468.09,4093.06 1513.37,4138.34 1513.37,4158.43 1555,4200.06 1598.04,4200.06 1612.2,4185.9 1612.2,4084.23 1631.37,4065.06 1688.57,4065.06 1717.91,4094.39 1717.91,4138.59 1737.37,4158.06 1944.58,4158.06 1980.33,4122.31 1980.33,4085.34 2016.92,4048.76 2087.42,4048.76 2116.3,4019.87 2174.18,4019.87 2369.37,4215.06 2369.37,4296.68 2277.76,4388.3 2213.07,4388.3 v1(2205.37,4396)
RADAR_LVDS_CLKP: J4.34 J10.44 | length 3859.5
  Top Layer w5.01: J10.44@629.09,2832.63 676.28,2832.63 679.12,2829.79 748.67,2829.79 v1(757.37,2838.49) ; J4.34@2081.5,4370.45 2112.5,4370.45 2115.35,4373.3 2196.67,4373.3 v1(2205.37,4364.6)
  L3-SIG1 w4.01: v1(757.37,2838.49) 751.36,2838.49 744.29,2845.56 744.29,2851.47 751.87,2859.06 771.78,2859.06 779.22,2851.62 779.22,2839.06 787.48,2830.79 794.1,2830.79 805,2841.69 805,2860.9 787.76,2878.14 787.76,2971.64 811.06,2994.94 811.06,3074.09 781.37,3103.78 781.37,3335.06 710.37,3406.06 710.37,3829.68 873.74,3993.06 873.74,4057.43 925.37,4109.06 1461.46,4109.06 1497.37,4144.97 1497.37,4165.06 1548.37,4216.06 1604.67,4216.06 1628.2,4192.53 1628.2,4090.85 1638,4081.06 1681.94,4081.06 1701.91,4101.02 1701.91,4145.22 1730.74,4174.06 1951.21,4174.06 1996.33,4128.94 1996.33,4091.97 2023.54,4064.76 2094.04,4064.76 2122.93,4035.87 2167.56,4035.87 2353.37,4221.68 2353.37,4290.06 2271.13,4372.3 2213.07,4372.3 v1(2205.37,4364.6)
RADAR_LVDS_FRCLKM: J4.30 J10.28 | length 3856.8
  Top Layer w5.01: J10.28@629.09,2990.11 676.28,2990.11 679.12,2992.96 691.37,2992.96 699.37,2984.96 v1(699.37,2984.26) ; J4.30@2081.5,4331.05 2112.5,4331.05 2115.35,4328.2 2240.67,4328.2 v1(2249.37,4336.9)
  L3-SIG1 w4.01: v1(699.37,2984.26) 707.07,2991.96 767.19,2991.96 792.57,3017.34 792.57,3060.68 762,3091.25 762,3303.66 689.37,3376.29 689.37,3843.06 848.37,4002.06 848.37,4079.06 899.37,4130.06 1438,4130.06 1471.37,4163.43 1471.37,4275.43 1499,4303.06 1609.37,4303.06 1640.37,4272.06 1640.37,4216.92 1661.23,4196.06 1809,4196.06 1831.37,4218.43 1831.37,4261.55 1847.88,4278.06 1896.82,4278.06 1917.37,4257.5 1917.37,4224.06 1939.18,4202.24 2008.2,4202.24 2013.6,4196.85 2043.5,4196.85 2072.37,4225.72 2072.37,4348.03 2084.71,4360.37 2102.86,4360.37 2114.3,4348.93 2114.3,4181.64 2134.64,4161.29 2171.12,4161.29 2197.88,4188.06 2285.88,4188.06 2327.07,4229.24 2327.07,4289.06 2286.93,4329.2 2257.07,4329.2 v1(2249.37,4336.9)
RADAR_LVDS_FRCLKP: J4.28 J10.26 | length 3857
  Top Layer w5.01: J10.26@629.09,3009.8 676.28,3009.8 679.12,3006.96 691.37,3006.96 699.37,3014.96 v1(699.37,3015.66) ; J4.28@2081.5,4311.35 2112.5,4311.35 2115.35,4314.2 2240.67,4314.2 v1(2249.37,4305.5)
  L3-SIG1 w4.01: v1(699.37,3015.66) 707.07,3007.96 760.56,3007.96 776.57,3023.97 776.57,3054.06 746,3084.63 746,3297.03 673.37,3369.66 673.37,3849.68 832.37,4008.68 832.37,4085.68 892.74,4146.06 1431.37,4146.06 1455.37,4170.06 1455.37,4282.06 1492.37,4319.06 1616,4319.06 1656.37,4278.68 1656.37,4223.55 1667.86,4212.06 1802.37,4212.06 1815.37,4225.06 1815.37,4268.17 1841.25,4294.06 1903.44,4294.06 1933.37,4264.13 1933.37,4230.68 1945.81,4218.24 2014.83,4218.24 2020.22,4212.85 2036.87,4212.85 2056.37,4232.35 2056.37,4354.65 2078.08,4376.37 2109.49,4376.37 2130.3,4355.55 2130.3,4188.26 2141.27,4177.29 2164.49,4177.29 2191.25,4204.06 2279.26,4204.06 2311.07,4235.87 2311.07,4282.43 2290.44,4303.06 2274.37,4303.06 2269.37,4298.06 2269.37,4282.06 2260.37,4273.06 2248.37,4273.06 2242.37,4279.06 2242.37,4298.5 v1(2249.37,4305.5)
RADAR_LVDS_VALIDM: J10.22 J17.22 | length 3849.1
  Top Layer w5.01: v1(441.37,4423.8) 450.07,4432.5 513.15,4432.5 516,4429.65 J17.22@547,4429.65 ; J10.22@629.09,3049.17 676.28,3049.17 679.12,3052.01 712.67,3052.01 v1(721.37,3043.31)
  L3-SIG1 w4.01: v1(441.37,4423.8) 449.07,4431.5 493.37,4431.5 542.37,4382.5 554.17,4370.7 600.58,4370.7 619,4352.28 619,4320.37 648.32,4291.06 738.25,4291.06 772.08,4324.89 772.08,4399.58 782.05,4409.55 810.54,4409.55 820.37,4399.72 820.37,4341.06 842.74,4318.68 881.31,4318.68 965.37,4402.74 965.37,4549.06 990.31,4574 1117.37,4574 1141.37,4550 1141.37,4391.43 1162.74,4370.06 1390.37,4370.06 1419.37,4341.06 1419.37,4217.06 1392.37,4190.06 882.37,4190.06 634.17,3941.86 634.17,3563.86 572.59,3502.27 572.59,3332.09 597.41,3307.26 619.34,3307.26 655.8,3270.8 655.8,3081.2 685.99,3051.01 713.67,3051.01 v1(721.37,3043.31)
RADAR_LVDS_VALIDP: J10.20 J17.20 | length 3849.1
  Top Layer w5.01: v1(441.37,4455.2) 450.07,4446.5 513.15,4446.5 516,4449.35 J17.20@547,4449.35 ; J10.20@629.09,3068.85 676.28,3068.85 679.12,3066.01 712.67,3066.01 v1(721.37,3074.71)
  L3-SIG1 w4.01: v1(441.37,4455.2) 449.07,4447.5 500,4447.5 560.79,4386.7 607.21,4386.7 635,4358.91 635,4327 654.94,4307.06 731.62,4307.06 756.08,4331.52 756.08,4406.21 775.42,4425.55 817.17,4425.55 836.37,4406.35 836.37,4347.68 849.37,4334.68 874.68,4334.68 949.37,4409.37 949.37,4555.68 983.69,4590 1124,4590 1157.37,4556.63 1157.37,4398.06 1169.37,4386.06 1397,4386.06 1435.37,4347.68 1435.37,4210.43 1399,4174.06 889,4174.06 650.17,3935.23 650.17,3557.23 588.59,3495.65 588.59,3338.71 604.04,3323.26 625.97,3323.26 671.8,3277.43 671.8,3087.83 692.61,3067.01 713.67,3067.01 v1(721.37,3074.71)
RADAR_MCUCLKOUT: J4.47 R359.1 R360.1 | length 149.1
  Top Layer w6: v1(1779.37,4489.06) 1780.25,4489.06 1799.54,4508.35 J4.47@1838.5,4508.35
  Bottom Layer w6: R359.1@1715.25,4445.99 1735.25,4445.99 1778.31,4489.06 v1(1779.37,4489.06)
RADAR_MSS_LOGGER_SPIB_CLK: J4.18 R161.1 U34.7 | length 4089.6
  Top Layer w6: v1(980.37,3441.06) 982.01,3442.69 R161.1@982.01,3463 ; v1(1995.37,4250.06) 1995.37,4236.79 2019.81,4212.35 2081,4212.35 J4.18@2081.5,4212.85
  L6-SIG2 w4.5: v1(980.37,3441.06) 980.37,3471.37 1001,3492 1001,3857.06 1204,4060.06 1909.06,4060.06 1940.43,4091.43 1940.43,4164.43 1995.37,4219.37 v1(1995.37,4250.06)
  L8-SIG3 w4: v1(980.37,3441.06) 979.37,3442.06 917.73,3442.06 799.46,3323.79 799.46,3103.54 826,3077 826,2874 924.18,2775.82 1010.38,2775.82 1043,2743.2 1043,2689.01 1064.6,2667.41 1064.6,2001.91 1042.71,1980.02 1042.71,1899.64 1086.76,1855.59 1157.41,1855.59 1208,1805 1246,1805 1267,1826 1328.76,1826 v1(1354.51,1800.24)
  Bottom Layer w6: U34.7@1330.87,1888.06 1330.87,1863.5 1319,1851.63 1319,1813.36 1332.12,1800.24 v1(1354.51,1800.24)
RADAR_NERR_IN: J4.52 R22.1 U27.10 | length 3517.2
  Top Layer w6: J4.52@2081.5,4547.75 2120.24,4547.75 v1(2139.37,4528.62)
  L5-PWR/SIG w4.5: v1(720.37,2260.06) 733.37,2260.06 751.95,2278.63 751.95,2288.53 811.84,2348.41 865.88,2348.41 877.32,2359.86 877.32,2448.32 969.04,2540.04 1003.92,2540.04 1048,2584.12 1048,2769 1089,2810 1089,2838.94 1266.37,3016.31 1266.37,3226.86 1266.57,3227.06 1266.57,3436.86 1252.17,3451.26 1252.17,4038.86 1864.51,4651.2 2132.23,4651.2 2163.37,4620.06 2163.37,4551.49 2139.94,4528.06 v1(2139.37,4528.62)
  Bottom Layer w6: U27.10@714.5,2213.55 714.5,2254.18 v1(720.37,2260.06)
  Bottom Layer w10: R22.1@2092.63,4516.99 2127.74,4516.99 v1(2139.37,4528.62)
RADAR_NERR_OUT: DS3.2 J4.54 R274.1 U26.10 | length 7166.6
  Top Layer w6: v1(623,57) 624,58 DS3.2@624,89.57 ; v1@1456.37,2492.06 1460.12,2488.31 U26.10@1460.12,2461.05 ; J4.54@2081.5,4567.45 2081.5,4568.2 2130.23,4568.2 v1(2139.37,4559.06)
  L5-PWR/SIG w4.5: v1(461.37,2612.06) 250,2400.69 250,2246 289,2207 289,2070 236.17,2017.17 236.17,1533.26 368.37,1401.06 368.37,945 292,868.63 292,388 v1(623,57)
  L6-SIG2 w4.5: v1(461.37,2612.06) 494.72,2645.4 626.06,2645.4 665.5,2605.96 665.5,2540.57 691.87,2514.2 801.8,2514.2 814.6,2527 863,2527 900.73,2489.27 1308.1,2489.27 1315.38,2481.99 1445.3,2481.99 v1(1456.37,2493.06)
  L8-SIG3 w4: v1(1456.37,2493.06) 1456.37,2508.06 1464.37,2516.06 1464.37,2541.06 1404.17,2601.26 1404.17,2780.72 1391.37,2793.52 1391.37,2840.06 1696,3144.69 1696,3290 1679,3307 1679,3494 1747.57,3562.57 1747.57,3815.42 1669.17,3893.82 1669.17,4035.17 1695.57,4061.57 1695.57,4162.86 1572.37,4286.06 1572.37,4389.11 1650.31,4467.06 1785.94,4467.06 1823.37,4504.49 1823.37,4597.31 1877.26,4651.2 1998.79,4651.2 2090.94,4559.06 v1(2139.37,4559.06)
  Bottom Layer w10: R274.1@2092.63,4567.99 2092.63,4568.2 2130.23,4568.2 v1(2139.37,4559.06)
RADAR_NRST: C24.2 J4.12 R74.1 R80.1 R117.1 R120.1 SW2.4 | length 3475.2
  Top Layer w6: v1(2013.37,4139.06) 2028.45,4139.06 2043.14,4153.75 J4.12@2081.5,4153.75 ; v1(2319.62,1864.53) R117.1@2351.94,1864.53 ; SW2.4@2686.5,2065.71 2686.5,2096.18 v1(2692.37,2102.06)
  L6-SIG2 w4.5: v1(2500,2375) 2500,2275.31 2603.37,2171.94 v1(2645.31,2171.94) 2673.11,2171.94 2692.37,2152.69 v1(2692.37,2102.06)
  L8-SIG3 w4: v1(2013.37,4139.06) 2065.37,4087.06 2065.37,3743.03 2199.57,3608.83 2199.57,2968.43 2252.57,2915.43 2252.57,2402.43 2280,2375 v1(2500,2375)
  Bottom Layer w6: v1(2319.62,1864.53) 2319.62,1865.62 2359,1905 2408,1905 2419,1894 2419,1872 2439,1852 2554.12,1852 2608.12,1906 2670.16,1906 2692.16,1928 2692.16,2101.84 v1(2692.37,2102.06) 2646.83,2102.06 2632.37,2087.6 R120.1@2632.37,2057.74 C24.2@2600.37,2057.74 ; R80.1@2589.69,2200 R74.1@2645.31,2200 v1(2645.31,2171.94)
RADAR_NRST_XDS: R129.1 U8.40 | length 3371.3
  Top Layer w6: v1(1359.37,3814.06) 1359.37,3816.03 1399.45,3856.11 1465.32,3856.11 1477.17,3844.26 2099.74,3844.26 2265,3679 v1(2265,3585) ; v1(2365,3260) 2365,3212 2507,3070 2507,2422 2465,2380 2465,2291.81 2525.43,2231.38 2652.68,2231.38 2718.37,2165.69 v1(2718.37,1914.06)
  L6-SIG2 w4.5: v1(2265,3585) 2265,3514 2334,3445 2334,3291 v1(2365,3260)
  Bottom Layer w6: R129.1@2710,1943.32 2710,1922.43 v1(2718.37,1914.06)
  Bottom Layer w8: U8.40@1267.48,3573.13 1267.48,3607.16 1319.04,3658.73 1319.04,3740.76 1329.37,3751.09 1329.37,3784.06 v1(1359.37,3814.06)
RADAR_OSC_CLKOUT: J4.45 R14.1 | length 748.5
  Top Layer w6: J4.45@1838.5,4488.65 1881.28,4488.65 v1(1885.45,4492.82) ; v1(2459.37,4588.06) 2460,4588.69 R14.1@2460,4619.02
  L6-SIG2 w4.5: v1(1885.45,4492.82) 1945.6,4492.82 1989.63,4448.8 2110.57,4448.8 2147.77,4486 2187.66,4486 2210.31,4463.35 2334.66,4463.35 v1(2459.37,4588.06)
RADAR_PMIC_CLKOUT_SOP2: J4.49 R131.1 R133.1 R347.1 R349.1 | length 5606.7
  Top Layer w6: v1(191.37,983.06) 199.44,974.99 R131.1@199.44,954.08 194.68,949.33 R133.1@194.68,906.74 ; v1(1790.63,4528) J4.49@1838.5,4528.05 J4.49@1838.5,4528.05
  L8-SIG3 w4: v1(191.37,983.06) 299,1090.69 299,1202 326,1229 326,1964 316.8,1973.2 316.8,2033.95 357.05,2074.2 395.8,2074.2 410.14,2059.86 477.37,2059.86 490.17,2047.06 551.37,2047.06 585.17,2080.86 665.14,2080.86 699.14,2046.86 824,2046.86 870,2092.86 870,2176.34 906.36,2212.7 906.36,2376.07 883.57,2398.86 883.57,2545.43 838,2591 838,2624 773.27,2688.73 773.27,2764.06 749.44,2787.89 ; 749.42,2787.89 675,2862.31 675,3192.89 731.37,3249.26 731.37,3340.55 883.37,3492.55 883.37,3590.56 945.06,3652.26 981.68,3652.26 998.68,3635.26 1140.65,3635.26 1220.05,3555.86 1418.57,3555.86 1454.92,3592.2 1584.08,3592.2 1675.57,3683.69 1675.57,3723.09 1555.37,3843.29 1555.37,4389.09 1694.29,4528 v1(1790.63,4528)
  Bottom Layer w6: R347.1@1715.25,4505 1743.74,4505 1766.74,4528 v1(1790.63,4528)
RADAR_RS232RX: J4.57 R247.1 U28.5 | length 3056.4
  Top Layer w6: U28.5@1417.24,2231.38 1447.38,2231.38 v1(1450,2234) ; J4.57@1838.5,4606.85 1879.48,4606.85 1885.63,4613 v1(1885.63,4631)
  L8-SIG3 w4: v1(1450,2234) 1450,2287.55 1464.17,2301.72 1464.17,2367.66 1513.37,2416.86 1513.37,2516.06 1475.06,2554.37 1475.06,2612.37 1455.37,2632.06 1433.37,2632.06 1416.17,2649.26 1416.17,2785.69 1412.17,2789.69 1412.17,2846.72 1706,3140.55 1706,3294.14 1690.8,3309.34 1690.8,3491.66 1759.57,3560.43 1759.57,3820.39 1707.57,3872.39 1707.57,4165 1584.37,4288.2 1584.37,4384.14 1655.28,4455.06 1799.37,4455.06 1835.37,4491.06 1835.37,4580.74 v1(1885.63,4631)
  Bottom Layer w6: R247.1@1854.01,4614.31 1870.7,4631 v1(1885.63,4631)
RADAR_RS232TX: J4.59 R73.1 U28.2 | length 4897.4
  Top Layer w6: v1(1327.49,2179.06) 1342.56,2194.13 1350.42,2194.13 1362.13,2205.84 U28.2@1362.13,2223.5
  Top Layer w8: v1(1773.25,4737.06) 1777.94,4737.06 1840.57,4674.43 1840.57,4628.61 J4.59@1838.5,4626.55
  L5-PWR/SIG w4.5: v1(1327.49,2179.06) 1255.49,2107.06 1033.05,2107.06 971.26,2045.27 859.21,2045.27 821.04,2007.1 821.04,1870.43 785.47,1834.86 692.06,1834.86 534.57,1992.35 534.57,2011.86 509.57,2036.86 493.57,2036.86 463.17,2067.26 463.17,2299.86 511.37,2348.06 561.94,2348.06 579.57,2365.69 579.57,2399.59 578.09,2401.07 578.09,2486.34 552.37,2512.06 552.37,2604.06 594.37,2646.06 594.37,3236.06 926.37,3568.06 926.37,4217.06 1446.57,4737.26 1773.05,4737.26 v1(1773.25,4737.06)
  Bottom Layer w6: R73.1@1740.05,4756.06 1754.25,4756.06 v1(1773.25,4737.06)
